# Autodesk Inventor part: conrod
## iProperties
Created: 2002-08
Part Number: conrod
Document SubType Name: Modeling
Designer: t_munrn
Density: 1 g/cm^3
Control State: 0
Master: False
Checked Out: False
Shininess: 64.0
Length Units: 11269
Angle Units: 11279
Time Units: 11290
Mass Units: 11283
Length Display Precision: 3
Angle Display Precision: 2
Density: 0.0
Volumn: 0.0
Area: 0.0
PropertySet Name: Model Information
Author: t_munrn
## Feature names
1. Extrusion1
2. Mirror1
3. Extrusion2
4. Fillet1
5. Hole1
6. Hole2
7. Extrusion3
8. Extrusion4
9. Fillet2
10. Mirror2
11. Fillet6
12. Fillet7
13. Chamfer1
14. Fillet4
15. Fillet5
